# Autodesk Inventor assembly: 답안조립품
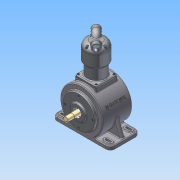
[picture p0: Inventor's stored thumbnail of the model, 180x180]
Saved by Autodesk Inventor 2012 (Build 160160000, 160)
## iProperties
Created: 2015-06
Part Number: 답안조립품
Document SubType Name: Assembly
Designer: User
Author: User
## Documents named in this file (14)
- C:\Documents and Settings\User\바탕 화면\450605V1018\답안조립품.iam
- C:\Documents and Settings\User\바탕 화면\450605V1018\본체.ipt
- C:\Documents and Settings\User\바탕 화면\450605V1018\메인커버.ipt
- C:\Documents and Settings\User\바탕 화면\450605V1018\M4x0.7.ipt
- C:\Documents and Settings\User\바탕 화면\450605V1018\베어링 6204.ipt
- C:\Documents and Settings\User\바탕 화면\450605V1018\메인 크랭크 축-구동부.ipt
- C:\Documents and Settings\User\바탕 화면\450605V1018\크랭크 서브축.ipt
- C:\Documents and Settings\User\바탕 화면\450605V1018\커넥팅 로드.ipt
- C:\Documents and Settings\User\바탕 화면\450605V1018\베어링 NA 4902.ipt
- C:\Documents and Settings\User\바탕 화면\450605V1018\피스톤 핀.ipt
- C:\Documents and Settings\User\바탕 화면\450605V1018\피스톤.ipt
- C:\Documents and Settings\User\바탕 화면\450605V1018\실린더헤드.ipt
- C:\Documents and Settings\User\바탕 화면\450605V1018\실린더.ipt
- C:\Documents and Settings\User\바탕 화면\450605V1018\M5x0.8.ipt
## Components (14 placed, 4 different names)
1. 피스톤 핀:1
2. 피스톤:1
3. M4x0.7:5
4. M4x0.7:6
5. M4x0.7:7
6. M4x0.7:8
7. M4x0.7:1
8. M4x0.7:2
9. M4x0.7:3
10. M4x0.7:4
11. M5x0.8:1
12. M5x0.8:2
13. M5x0.8:3
14. M5x0.8:4
